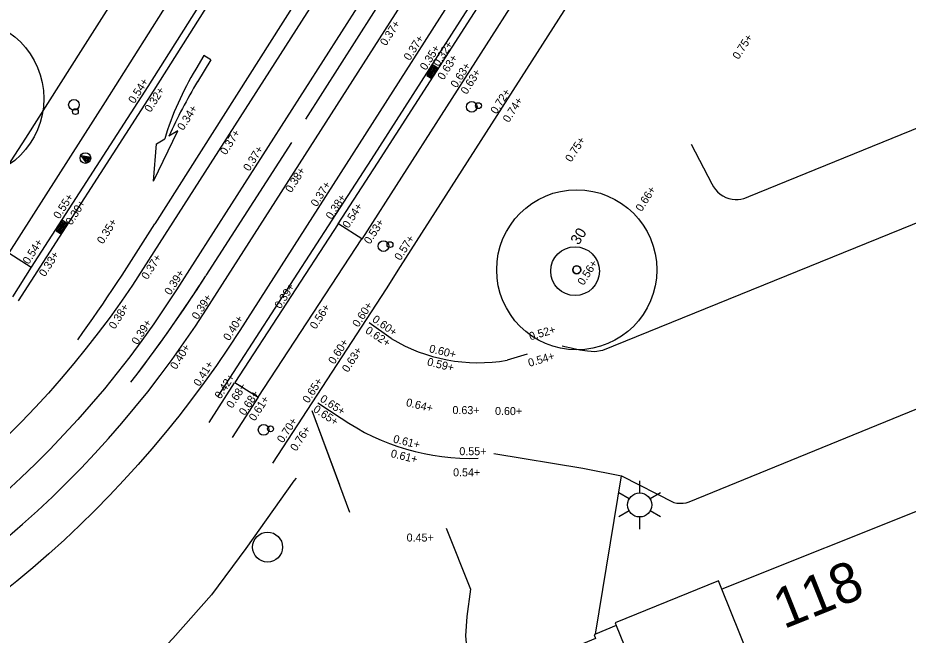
# Model space of a CAD drawing. Extents: x 122462 to 123306, y 485548 to 486417.
# Drawn here: x 122843.63 to 122876.99, y 485753.45 to 485776.58 of the extents above; entities that cross this region are included whole.
import ezdxf

# ---------------------------------------------------------------- set-up
doc = ezdxf.new("R2010")
doc.units = 0
for name, color, linetype in [('B-WE-GR-BOOM-S', 7, 'Continuous'), ('B-WE-GR-BOOM_BOOMDIAMETER', 7, 'Continuous'), ('B-WE-IE-MEUBILAIR_WEGMEUBILAIR-S', 7, 'Continuous'), ('B-WE-OG-HOOGTEPUNT-S', 7, 'Continuous'), ('B-WE-RI-HWA_KOLK-S', 7, 'Continuous'), ('B-WE-VH-KANTOPSLUITING_ELEMENT_INRIT-S', 7, 'Continuous'), ('B-WE-VH-KANTOPSLUITING_TROTTOIRBAND_130 150-G', 7, 'Continuous'), ('B-WE-VH-KANTOPSLUITING_TROTTOIRBAND_280 300-G', 7, 'Continuous'), ('B-WE-VH-KANTOPSLUITING_TROTTOIRBAND_NATUURSTEEN_150-G', 7, 'Continuous'), ('B-WE-VH-KANTOPSLUITING_TROTTOIRBAND_NATUURSTEEN_300-G', 7, 'Continuous'), ('B-WE-VH-KANTVERHARDING_EIND_VERHARDING-G', 7, 'Continuous'), ('B-WE-VH-MATERIAALGRENS-G', 7, 'Continuous'), ('B-WE-VH-MATERIAALGRENS_ASFALT-G', 7, 'Continuous'), ('B-WE-VW-MARKERING_LANGS_STREEP_11_010-G', 7, 'Continuous'), ('B-WE-VW-MARKERING_LANGS_STREEP_DOORGETROKKEN_010-G', 7, 'Continuous'), ('B-WE-VW-MARKERING_OVERIG-G', 7, 'Continuous'), ('B-WE-VW-MARKERING_PIJL-S', 7, 'Continuous'), ('Level 1', 7, 'Continuous'), ('Level 17', 7, 'Continuous'), ('Level 23', 7, 'Continuous'), ('Level 37', 7, 'Continuous'), ('Level 50', 7, 'Continuous'), ('Level 53', 7, 'Continuous'), ('Level 58', 7, 'Continuous')]:
    doc.layers.add(name, color=color, linetype=linetype)

msp = doc.modelspace()

# ---------------------------------------------------------------- linework, layer by layer
at = {"layer": 'B-WE-GR-BOOM-S'}
for centre, radius in [((122841.608, 485773.552), 3), ((122864.573, 485767.136), 3), ((122864.573, 485767.136), 0.15)]:
    msp.add_circle(centre, radius, dxfattribs=at)
for start, end in [(0, 180), (180, 0)]:
    msp.add_arc((122864.573, 485767.136), 0.15, start, end, dxfattribs=at)
at = {"layer": 'B-WE-IE-MEUBILAIR_WEGMEUBILAIR-S'}
msp.add_lwpolyline([(122846.346, 485771.353), (122846.21, 485771.141), (122846.006, 485771.422), (122846.308, 485771.364), (122846.208, 485771.208), (122846.078, 485771.376), (122846.243, 485771.337), (122846.206, 485771.279), (122846.179, 485771.311), (122846.137, 485771.339)], dxfattribs=at)
msp.add_circle((122846.162, 485771.322), 0.2, dxfattribs=at)
at = {"layer": 'B-WE-RI-HWA_KOLK-S'}
for p, q in [((122859.194, 485774.796), (122858.951, 485774.417)), ((122859.363, 485774.688), (122859.194, 485774.796)), ((122858.951, 485774.417), (122859.12, 485774.309)), ((122859.12, 485774.309), (122859.363, 485774.688)), ((122845.308, 485768.978), (122845.066, 485768.599)), ((122845.235, 485768.491), (122845.477, 485768.871)), ((122845.477, 485768.871), (122845.308, 485768.978)), ((122845.066, 485768.599), (122845.235, 485768.491))]:
    msp.add_line(p, q, dxfattribs=at)
for points in [[(122859.199, 485774.714), (122859.216, 485774.741), (122859.304, 485774.685), (122859.287, 485774.658), (122859.199, 485774.714)], [(122859.01, 485774.42), (122859.027, 485774.447), (122859.115, 485774.39), (122859.098, 485774.363), (122859.01, 485774.42)], [(122859.037, 485774.462), (122859.054, 485774.489), (122859.142, 485774.433), (122859.125, 485774.406), (122859.037, 485774.462)], [(122859.064, 485774.504), (122859.081, 485774.531), (122859.169, 485774.475), (122859.152, 485774.448), (122859.064, 485774.504)], [(122859.091, 485774.546), (122859.108, 485774.573), (122859.196, 485774.517), (122859.179, 485774.49), (122859.091, 485774.546)], [(122859.118, 485774.588), (122859.135, 485774.615), (122859.223, 485774.559), (122859.206, 485774.532), (122859.118, 485774.588)], [(122859.145, 485774.63), (122859.162, 485774.657), (122859.25, 485774.601), (122859.233, 485774.574), (122859.145, 485774.63)], [(122859.172, 485774.672), (122859.189, 485774.699), (122859.277, 485774.643), (122859.26, 485774.616), (122859.172, 485774.672)], [(122845.206, 485768.728), (122845.223, 485768.755), (122845.311, 485768.699), (122845.293, 485768.672), (122845.206, 485768.728)], [(122845.232, 485768.771), (122845.25, 485768.798), (122845.338, 485768.742), (122845.32, 485768.715), (122845.232, 485768.771)], [(122845.259, 485768.813), (122845.277, 485768.84), (122845.364, 485768.784), (122845.347, 485768.757), (122845.259, 485768.813)], [(122845.286, 485768.855), (122845.303, 485768.882), (122845.391, 485768.826), (122845.374, 485768.799), (122845.286, 485768.855)], [(122845.313, 485768.897), (122845.33, 485768.924), (122845.418, 485768.868), (122845.401, 485768.841), (122845.313, 485768.897)], [(122845.125, 485768.602), (122845.142, 485768.629), (122845.23, 485768.573), (122845.213, 485768.546), (122845.125, 485768.602)], [(122845.152, 485768.644), (122845.169, 485768.671), (122845.257, 485768.615), (122845.24, 485768.588), (122845.152, 485768.644)], [(122845.179, 485768.686), (122845.196, 485768.713), (122845.284, 485768.657), (122845.267, 485768.63), (122845.179, 485768.686)]]:
    msp.add_lwpolyline(points, dxfattribs=at)
at = {"layer": 'B-WE-VH-KANTOPSLUITING_ELEMENT_INRIT-S'}
for points in [[(122855.639, 485768.855), (122851.756, 485762.921), (122852.632, 485762.366), (122856.523, 485768.3), (122855.665, 485768.851)], [(122842.582, 485766.659), (122843.295, 485767.772), (122844.137, 485767.233), (122843.426, 485766.12)]]:
    msp.add_lwpolyline(points, dxfattribs=at)
at = {"layer": 'B-WE-VH-KANTOPSLUITING_TROTTOIRBAND_130 150-G'}
msp.add_lwpolyline([(122859.545, 485796.675), (122857.941, 485794.118), (122851.457, 485783.939), (122846.068, 485775.456), (122843.914, 485772.069), (122842.809, 485770.365)], dxfattribs=at)
at = {"layer": 'B-WE-VH-KANTOPSLUITING_TROTTOIRBAND_280 300-G'}
for points in [[(122855.639, 485768.855), (122857.113, 485771.127), (122861.998, 485778.754), (122863.08, 485780.447)], [(122857.62, 485764.568), (122856.791, 485765.148)], [(122862.717, 485763.972), (122861.963, 485763.749)], [(122854.876, 485762.153), (122855.751, 485761.577)]]:
    msp.add_lwpolyline(points, dxfattribs=at)
for centre, radius, start, end in [((122860.876, 485769.912), 6.258, 238.6422, 279.999), ((122860.582, 485768.576), 8.504, 235.3856, 272.0108)]:
    msp.add_arc(centre, radius, start, end, dxfattribs=at)
at = {"layer": 'B-WE-VH-KANTOPSLUITING_TROTTOIRBAND_NATUURSTEEN_150-G'}
for points in [[(122859.545, 485796.675), (122857.941, 485794.118), (122851.457, 485783.939), (122846.068, 485775.456), (122843.914, 485772.069), (122842.809, 485770.365)], [(122843.305, 485767.77), (122846.914, 485773.426), (122850.68, 485779.38), (122854.452, 485785.317), (122859.842, 485793.813), (122860.927, 485795.506)], [(122863.946, 485779.905), (122856.523, 485768.29)], [(122853.181, 485759.893), (122857.443, 485766.425), (122857.974, 485767.266), (122865.019, 485778.277)], [(122852.632, 485762.366), (122851.667, 485760.86)]]:
    msp.add_lwpolyline(points, dxfattribs=at)
at = {"layer": 'B-WE-VH-KANTOPSLUITING_TROTTOIRBAND_NATUURSTEEN_300-G'}
for points in [[(122858.729, 485790.164), (122853.344, 485781.672), (122848.499, 485774.007), (122844.135, 485767.235)], [(122855.639, 485768.855), (122857.113, 485771.127), (122861.998, 485778.754), (122863.08, 485780.447)], [(122850.798, 485761.415), (122851.747, 485762.904)]]:
    msp.add_lwpolyline(points, dxfattribs=at)
at = {"layer": 'B-WE-VH-KANTVERHARDING_EIND_VERHARDING-G'}
msp.add_circle((122864.511, 485767.087), 0.913, dxfattribs=at)
at = {"layer": 'B-WE-VH-MATERIAALGRENS-G'}
for points in [[(122856.071, 485758.049), (122854.66, 485761.853)], [(122855.693, 485759.068), (122854.66, 485761.853)]]:
    msp.add_lwpolyline(points, dxfattribs=at)
at = {"layer": 'B-WE-VH-MATERIAALGRENS_ASFALT-G'}
for points in [[(122858.956, 485790.018), (122853.572, 485781.528), (122848.727, 485773.862), (122843.647, 485765.979)], [(122855.412, 485769.002), (122856.886, 485771.273), (122861.771, 485778.9), (122862.852, 485780.591)], [(122851.132, 485762.4), (122855.412, 485769.002)]]:
    msp.add_lwpolyline(points, dxfattribs=at)
at = {"layer": 'B-WE-VW-MARKERING_LANGS_STREEP_11_010-G'}
msp.add_lwpolyline([(122853.89, 485771.901), (122850.678, 485766.917)], dxfattribs=at)
for start in [322.1044, 322.444]:
    msp.add_arc((122806.883, 485794.821), 51.93, start, 327.4965, dxfattribs=at)
at = {"layer": 'B-WE-VW-MARKERING_LANGS_STREEP_DOORGETROKKEN_010-G'}
for points in [[(122854.426, 485772.777), (122858.88, 485779.781), (122861.114, 485783.283)], [(122856.618, 485781.242), (122848.765, 485768.861)]]:
    msp.add_lwpolyline(points, dxfattribs=at)
msp.add_arc((122772.866, 485816.081), 89.389, 324.76929, 328.11262, dxfattribs=at)
at = {"layer": 'B-WE-VW-MARKERING_OVERIG-G'}
for centre, radius in [((122845.734, 485773.317), 0.2), ((122860.639, 485773.243), 0.2), ((122845.788, 485773.062), 0.11), ((122860.891, 485773.284), 0.11), ((122857.333, 485768.025), 0.2), ((122857.577, 485768.08), 0.11), ((122852.842, 485761.139), 0.2), ((122853.1, 485761.178), 0.11)]:
    msp.add_circle(centre, radius, dxfattribs=at)
at = {"layer": 'B-WE-VW-MARKERING_PIJL-S'}
for p, q in [((122850.606, 485775.161), (122850.296, 485774.648)), ((122850.862, 485775.007), (122850.606, 485775.161)), ((122850.862, 485775.007), (122850.367, 485774.184)), ((122848.719, 485770.461), (122849.621, 485772.346)), ((122849.621, 485772.346), (122849.286, 485772.139)), ((122848.719, 485770.461), (122848.833, 485771.851)), ((122848.833, 485771.851), (122849.135, 485772.043))]:
    msp.add_line(p, q, dxfattribs=at)
for centre, radius, start, end in [((122860.175, 485768.683), 11.54, 148.8805, 163.0747), ((122867.498, 485763.824), 20.02, 148.8357, 155.461)]:
    msp.add_arc(centre, radius, start, end, dxfattribs=at)
at = {"layer": 'Level 1'}
for points in [[(122870.013, 485755.167), (122869.887, 485755.485), (122866.007, 485753.915), (122866.048, 485753.813)], [(122878.01, 485739.303), (122876.627, 485738.747), (122870.013, 485755.167)], [(122866.048, 485753.813), (122872.691, 485737.485), (122865.496, 485734.521), (122858.844, 485750.869)]]:
    msp.add_lwpolyline(points, dxfattribs=at)
at = {"layer": 'Level 17'}
msp.add_line((122865.274, 485753.482), (122866.245, 485759.422), dxfattribs=at)
for points in [[(122870.514, 485769.768), (122870.62, 485769.769), (122870.726, 485769.782), (122870.83, 485769.806), (122870.931, 485769.841), (122871.027, 485769.886), (122904.324, 485783.439), (122911.897, 485786.521), (122912.102, 485786.622), (122912.299, 485786.735), (122912.49, 485786.861), (122912.672, 485786.998), (122912.845, 485787.146), (122913.009, 485787.305), (122913.162, 485787.474)], [(122905.513, 485780.351), (122865.539, 485764.111), (122865.257, 485764.062), (122864.975, 485764.091), (122864.694, 485764.132), (122864.415, 485764.184), (122864.358, 485764.196), (122864.126, 485764.25), (122864.03, 485764.276)], [(122868.856, 485771.838), (122869.637, 485770.357), (122869.695, 485770.248), (122869.766, 485770.147), (122869.849, 485770.055), (122869.942, 485769.975), (122870.045, 485769.906), (122870.155, 485769.85), (122870.271, 485769.808), (122870.391, 485769.781), (122870.514, 485769.768)], [(122866.245, 485759.422), (122868.212, 485758.424), (122868.325, 485758.4), (122868.44, 485758.389), (122868.555, 485758.392), (122868.67, 485758.409), (122868.781, 485758.44), (122895.541, 485769.368)], [(122861.462, 485760.253), (122864.798, 485759.7), (122866.245, 485759.422)], [(122854.059, 485759.333), (122853.977, 485759.226), (122852.17, 485756.699), (122850.89, 485754.959), (122849.445, 485753.329), (122849.238, 485753.107), (122849.02, 485752.896), (122848.792, 485752.697), (122848.554, 485752.509), (122848.307, 485752.333), (122848.051, 485752.17), (122847.787, 485752.02), (122847.516, 485751.884), (122847.239, 485751.761), (122844.096, 485750.468), (122830.088, 485744.703), (122826.859, 485743.334)], [(122859.679, 485757.46), (122860.59, 485755.179), (122860.46, 485754.149), (122860.41, 485753.429), (122860.45, 485752.879), (122860.872, 485751.632)]]:
    msp.add_lwpolyline(points, dxfattribs=at)
at = {"layer": 'Level 23'}
for p, q in [((122878.088, 485758.399), (122870.013, 485755.167)), ((122866.048, 485753.813), (122865.274, 485753.482))]:
    msp.add_line(p, q, dxfattribs=at)
msp.add_lwpolyline([(122865.274, 485753.482), (122865.22, 485753.459), (122865.27, 485753.329), (122860.91, 485751.5)], dxfattribs=at)
at = {"layer": 'Level 37'}
for points in [[(122864.275, 485791.284), (122864.002, 485790.971), (122863.492, 485790.364), (122862.995, 485789.747), (122862.511, 485789.12), (122862.038, 485788.484), (122861.579, 485787.838), (122861.132, 485787.184), (122860.699, 485786.521), (122848.328, 485767.181), (122847.926, 485766.567), (122847.512, 485765.961), (122847.086, 485765.364), (122846.647, 485764.775), (122846.197, 485764.196), (122845.735, 485763.626), (122845.261, 485763.066), (122844.776, 485762.515), (122844.28, 485761.974), (122843.773, 485761.444), (122843.256, 485760.924)], [(122865.327, 485790.24), (122865.127, 485790.01), (122864.636, 485789.425), (122864.158, 485788.831), (122863.691, 485788.227), (122863.236, 485787.615), (122862.794, 485786.993), (122862.364, 485786.363), (122861.946, 485785.724), (122849.575, 485766.384), (122849.157, 485765.745), (122848.726, 485765.114), (122848.282, 485764.492), (122847.825, 485763.88), (122847.357, 485763.276), (122846.875, 485762.683), (122846.382, 485762.099), (122845.878, 485761.526), (122845.361, 485760.963), (122844.833, 485760.411), (122844.294, 485759.869), (122843.744, 485759.339), (122843.184, 485758.82)], [(122867.391, 485788.19), (122867.164, 485787.932), (122866.661, 485787.338), (122866.17, 485786.733), (122865.692, 485786.118), (122865.226, 485785.494), (122864.773, 485784.86), (122864.333, 485784.217), (122863.907, 485783.565), (122851.945, 485764.867), (122851.514, 485764.207), (122851.069, 485763.555), (122850.612, 485762.912), (122850.142, 485762.278), (122849.659, 485761.653), (122849.164, 485761.039), (122848.658, 485760.434), (122848.139, 485759.839)], [(122843.235, 485757.104), (122843.809, 485757.603), (122844.372, 485758.112), (122844.926, 485758.633), (122845.469, 485759.165), (122846.001, 485759.707), (122846.522, 485760.26), (122847.033, 485760.823), (122847.532, 485761.395), (122848.02, 485761.978), (122848.497, 485762.57), (122848.961, 485763.171), (122849.414, 485763.782), (122849.855, 485764.401), (122850.283, 485765.028), (122850.699, 485765.665), (122862.66, 485784.363)], [(122848.139, 485759.839), (122847.609, 485759.255), (122847.067, 485758.681), (122846.515, 485758.118), (122845.951, 485757.566), (122845.376, 485757.025), (122844.791, 485756.495), (122844.195, 485755.978), (122843.59, 485755.472), (122842.974, 485754.978), (122842.349, 485754.496), (122841.715, 485754.027), (122841.071, 485753.571), (122840.419, 485753.127)]]:
    msp.add_lwpolyline(points, dxfattribs=at)
at = {"layer": 'Level 50'}
for p, q in [((122866.931, 485758.777), (122866.931, 485759.227)), ((122866.541, 485758.552), (122866.151, 485758.777)), ((122867.71, 485758.777), (122867.32, 485758.552)), ((122866.541, 485758.102), (122866.151, 485757.877)), ((122867.71, 485757.877), (122867.32, 485758.102)), ((122866.931, 485757.427), (122866.931, 485757.877))]:
    msp.add_line(p, q, dxfattribs=at)
msp.add_circle((122866.931, 485758.327), 0.45, dxfattribs=at)
at = {"layer": 'Level 53'}
msp.add_circle((122852.99, 485756.749), 0.56, dxfattribs=at)

# ---------------------------------------------------------------- texts
at = {"layer": 'B-WE-GR-BOOM_BOOMDIAMETER'}
msp.add_text('30', height=0.4, rotation=57.3883, dxfattribs=at).set_placement((122864.643, 485768.039))
at = {"layer": 'B-WE-OG-HOOGTEPUNT-S'}
for s, rotation, p in [('0.37+', 57.5468, (122857.429, 485775.502)), ('0.37+', 57.5468, (122858.315, 485774.95)), ('0.75+', 57.4653, (122870.638, 485774.993)), ('0.35+', 57.5468, (122858.921, 485774.586)), ('0.32+', 57.5468, (122859.405, 485774.729)), ('0.63+', 57.5468, (122859.581, 485774.224)), ('0.63+', 57.5468, (122860.07, 485773.926)), ('0.63+', 57.5468, (122860.451, 485773.682)), ('0.54+', 57.4587, (122847.996, 485773.339)), ('0.32+', 57.4587, (122848.603, 485773.011)), ('0.72+', 57.5468, (122861.566, 485772.946)), ('0.74+', 57.5468, (122862.028, 485772.628)), ('0.34+', 57.4587, (122849.83, 485772.332)), ('0.37+', 57.6139, (122851.435, 485771.414)), ('0.75+', 57.3883, (122864.366, 485771.147)), ('0.37+', 57.6139, (122852.303, 485770.805)), ('0.38+', 57.6139, (122853.878, 485770.001)), ('0.37+', 57.6139, (122854.831, 485769.474)), ('0.66+', 57.3883, (122867.004, 485769.294)), ('0.55+', 57.4587, (122845.187, 485769.017)), ('0.38+', 57.0143, (122855.394, 485768.997)), ('0.30+', 57.4587, (122845.643, 485768.785)), ('0.54+', 57.0143, (122856.019, 485768.667)), ('0.35+', 57.4587, (122846.821, 485768.077)), ('0.53+', 57.0143, (122856.823, 485768.069)), ('0.54+', 57.4587, (122844.039, 485767.318)), ('0.57+', 57.3883, (122857.966, 485767.46)), ('0.33+', 57.4587, (122844.648, 485766.853)), ('0.37+', 57.6139, (122848.487, 485766.746)), ('0.56+', 57.3883, (122864.828, 485766.53)), ('0.39+', 57.6139, (122849.348, 485766.165)), ('0.39+', 56.7967, (122853.47, 485765.65)), ('0.39+', 57.6139, (122850.373, 485765.248)), ('0.38+', 57.6139, (122847.265, 485764.888)), ('0.56+', 56.7967, (122854.794, 485764.886)), ('0.60+', 56.8754, (122856.39, 485764.961)), ('0.60+', 325.0219, (122856.883, 485765.217)), ('0.39+', 57.6139, (122848.117, 485764.305)), ('0.40+', 57.6139, (122851.553, 485764.453)), ('0.62+', 326.6437, (122856.624, 485764.793)), ('0.52+', 16.4759, (122862.838, 485764.489)), ('0.60+', 57.3883, (122855.489, 485763.575)), ('0.40+', 57.6139, (122849.563, 485763.377)), ('0.63+', 57.3883, (122856.003, 485763.269)), ('0.60+', 346.2624, (122859.022, 485764.055)), ('0.59+', 346.2624, (122858.947, 485763.559)), ('0.54+', 16.4759, (122862.799, 485763.498)), ('0.41+', 57.6139, (122850.437, 485762.745)), ('0.42+', 56.7967, (122851.226, 485762.273)), ('0.68+', 56.7967, (122851.667, 485761.923)), ('0.65+', 56.8754, (122854.518, 485762.117)), ('0.68+', 56.7967, (122852.137, 485761.653)), ('0.65+', 326.6437, (122854.925, 485762.232)), ('0.61+', 56.7967, (122852.51, 485761.445)), ('0.65+', 326.6437, (122854.669, 485761.844)), ('0.64+', 346.2624, (122858.156, 485762.04)), ('0.63+', 359.7303, (122859.916, 485761.733)), ('0.60+', 359.7303, (122861.511, 485761.698)), ('0.70+', 56.8754, (122853.565, 485760.626)), ('0.76+', 56.8754, (122854.062, 485760.316)), ('0.61+', 346.2624, (122857.674, 485760.672)), ('0.61+', 346.2624, (122857.582, 485760.126)), ('0.54+', 359.7303, (122859.939, 485759.401))]:
    msp.add_text(s, height=0.3, rotation=rotation, dxfattribs=at).set_placement(p)
for s, p in [('0.55+', (122860.175, 485760.191)), ('0.45+', (122858.199, 485756.957))]:
    msp.add_text(s, height=0.3, dxfattribs=at).set_placement(p)
at = {"layer": 'Level 58'}
msp.add_text('118', height=1.5, rotation=21.8133, dxfattribs=at).set_placement((122872.331, 485753.671))

doc.saveas('drawing.dxf')
